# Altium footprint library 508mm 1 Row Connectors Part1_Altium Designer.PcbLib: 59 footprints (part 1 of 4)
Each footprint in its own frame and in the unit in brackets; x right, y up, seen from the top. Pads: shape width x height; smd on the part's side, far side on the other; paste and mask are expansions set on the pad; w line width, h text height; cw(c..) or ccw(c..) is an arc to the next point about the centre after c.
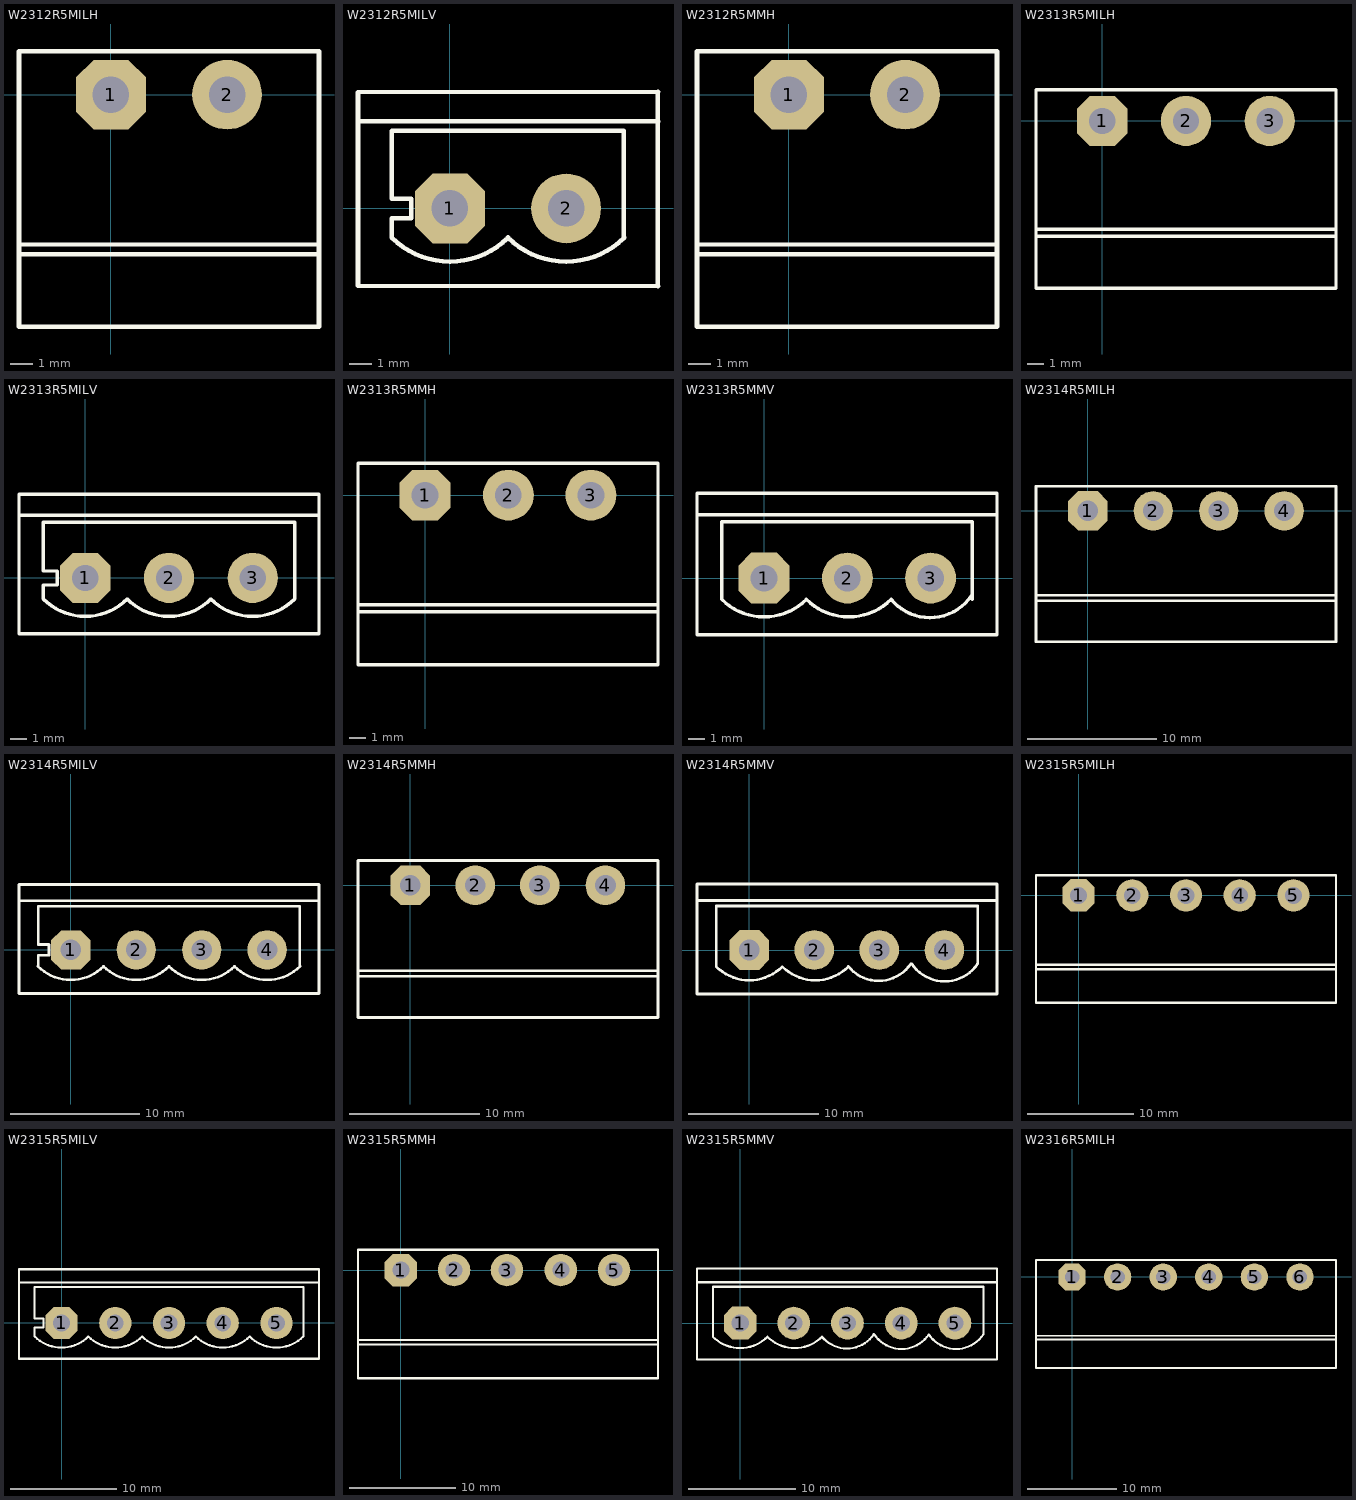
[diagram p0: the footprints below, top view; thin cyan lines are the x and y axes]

## W2312R5MILH [mil] "M.Hariri (Altium Designer)"
pads (2):
  oct 120x120 hole 62.99: 1(0,0)
  round 120 hole 62.99: 2(200,0)
Top Overlay:
  lines w8: -158.33,-275 355,-275 ; -158.33,-258.33 357.5,-257.5 ; -158.33,-400 358.33,-400 358.33,75 -158.33,75 -158.33,-400

## W2312R5MILV [mil] "M.Hariri (Altium Designer)"
pads (2):
  oct 120x120 hole 62.99: 1(0,0)
  round 120 hole 62.99: 2(200,0)
Top Overlay:
  lines w8: -158.33,150 358.27,149.61 ; -100.17,-50.17 ccw(c0,50) 100.17,-50.17 ; -100,-50 -100,-16.67 -66.67,-16.67 -66.67,16.67 -100,16.67 -100,133.33 299.21,133.86 ; 99.83,-50.17 ccw(c200,50) 300.17,-50.17 ; 299.21,-50 299.21,133.33 ; 357.55,-133.33 357.55,200 ; 358.27,-133.86 -158.33,-133.33 -158.33,200 358.27,200.79

## W2312R5MMH [mil] "M.Hariri (Altium Designer)"
pads (2):
  oct 120x120 hole 62.99: 1(0,0)
  round 120 hole 62.99: 2(200,0)
Top Overlay:
  lines w8: -158.33,-275 355,-275 ; -158.33,-258.33 357.5,-257.5 ; -158.33,-400 -158.33,75 358.33,75 358.33,-400 -158.33,-400

## W2313R5MILH [mil] "M.Hariri (Altium Designer)"
pads (3):
  oct 120x120 hole 62.99: 1(0,0)
  round 120 hole 62.99: 2(200,0) 3(400,0)
Top Overlay:
  lines w8: -158.33,-275 558.33,-275 ; -158.33,-258.33 558.33,-258.33 ; -158.33,-400 558.33,-400 558.33,75 -158.33,75 -158.33,-400

## W2313R5MILV [mil] "M.Hariri (Altium Designer)"
pads (3):
  oct 120x120 hole 62.99: 1(0,0)
  round 120 hole 62.99: 2(200,0) 3(400,0)
Top Overlay:
  lines w8: -158.33,150 558.33,150 ; -100.17,-50.17 ccw(c0,50) 100.17,-50.17 ; -100,-50 -100,-16.67 -66.67,-16.67 -66.67,16.67 -100,16.67 -100,133.33 500,133.33 500,-50 ; 99.83,-50.17 ccw(c200,50) 300.17,-50.17 ; 299.83,-50.17 ccw(c400,50) 500.17,-50.17 ; -158.33,-133.33 -158.33,200 558.33,200 558.33,-133.33 -158.33,-133.33

## W2313R5MMH [mil] "M.Hariri (Altium Designer)"
pads (3):
  oct 120x120 hole 62.99: 1(0,0)
  round 120 hole 62.99: 2(196.67,0) 3(391.67,0)
Top Overlay:
  lines w8: -158.33,-275 550,-275 ; -158.33,-258.33 550,-258.33 ; -158.33,-400 550,-400 550,75 -158.33,75 -158.33,-400

## W2313R5MMV [mil] "M.Hariri (Altium Designer)"
pads (3):
  oct 120x120 hole 62.99: 1(0,0)
  round 120 hole 62.99: 2(196.67,0) 3(393.33,0)
Top Overlay:
  lines w8: -158.33,150 550,150 ; -100.17,-50.17 ccw(c0,50) 100.17,-50.17 ; -100,-50 -100,133.33 491.67,133.33 491.67,-50 ; 99.83,-50.17 ccw(c200,50) 300.17,-50.17 ; 299.7,-49.47 ccw(c391.67,25) 489.77,-41.17 ; -158.33,-133.33 -158.33,200 550,200 550,-133.33 -158.33,-133.33

## W2314R5MILH [mil] "M.Hariri (Altium Designer)"
pads (4):
  oct 120x120 hole 62.99: 1(0,0)
  round 120 hole 62.99: 2(200,0) 3(400,0) 4(600,0)
Top Overlay:
  lines w8: -158.33,-275 758.33,-275 ; -158.33,-258.33 758.33,-258.33 ; -158.33,-400 758.33,-400 758.33,75 -158.33,75 -158.33,-400

## W2314R5MILV [mil] "M.Hariri (Altium Designer)"
pads (4):
  oct 120x120 hole 62.99: 1(0,0)
  round 120 hole 62.99: 2(200,0) 3(400,0) 4(600,0)
Top Overlay:
  lines w8: -158.33,150 758.33,150 ; -100.17,-50.17 ccw(c0,50) 100.17,-50.17 ; -100,-50 -100,-16.67 -66.67,-16.67 -66.67,16.67 -100,16.67 -100,133.33 700,133.33 700,-50 ; 99.83,-50.17 ccw(c200,50) 300.17,-50.17 ; 299.83,-50.17 ccw(c400,50) 500.17,-50.17 ; 499.83,-50.17 ccw(c600,50) 700.17,-50.17 ; -158.33,-133.33 758.33,-133.33 758.33,200 -158.33,200 -158.33,-133.33

## W2314R5MMH [mil] "M.Hariri (Altium Designer)"
pads (4):
  oct 120x120 hole 62.99: 1(0,0)
  round 120 hole 62.99: 2(196.67,0) 3(391.67,0) 4(590.83,0)
Top Overlay:
  lines w8: -158.33,-275 750,-275 ; -158.33,-258.33 750,-258.33 ; -158.33,-400 750,-400 750,75 -158.33,75 -158.33,-400

## W2314R5MMV [mil] "M.Hariri (Altium Designer)"
pads (4):
  oct 120x120 hole 62.99: 1(0,0)
  round 120 hole 62.99: 2(196.67,0) 3(393.33,0) 4(590.83,0)
Top Overlay:
  lines w8: -158.33,150 750,150 ; -100.17,-50.17 ccw(c0,50) 100.17,-50.17 ; -100,-50 -100,133.33 691.67,133.33 691.67,-41.67 ; 99.83,-50.17 ccw(c200,50) 300.17,-50.17 ; 299.7,-49.47 ccw(c391.67,25) 489.77,-41.17 ; 492.18,-42.1 ccw(c591.67,25) 691.15,-42.1 ; -158.33,-133.33 -158.33,200 750,200 750,-133.33 -158.33,-133.33

## W2315R5MILH [mil] "M.Hariri (Altium Designer)"
pads (5):
  oct 120x120 hole 62.99: 1(0,0)
  round 120 hole 62.99: 2(200,0) 3(400,0) 4(600,0) 5(800,0)
Top Overlay:
  lines w8: -158.33,-275 958.33,-275 ; -158.33,-258.33 958.33,-258.33 ; -158.33,-400 958.33,-400 958.33,75 -158.33,75 -158.33,-400

## W2315R5MILV [mil] "M.Hariri (Altium Designer)"
pads (5):
  oct 120x120 hole 62.99: 1(0,0)
  round 120 hole 62.99: 2(200,0) 3(400,0) 4(600,0) 5(800,0)
Top Overlay:
  lines w8: -158.33,150 958.33,150 ; -100.17,-50.17 ccw(c0,50) 100.17,-50.17 ; -100,-50 -100,-16.67 -66.67,-16.67 -66.67,16.67 -100,16.67 -100,133.33 900,133.33 900,-50 ; 99.83,-50.17 ccw(c200,50) 300.17,-50.17 ; 299.83,-50.17 ccw(c400,50) 500.17,-50.17 ; 499.83,-50.17 ccw(c600,50) 700.17,-50.17 ; 699.83,-50.17 ccw(c800,50) 900.17,-50.17 ; -158.33,-133.33 -158.33,200 958.33,200 958.33,-133.33 -158.33,-133.33

## W2315R5MMH [mil] "M.Hariri (Altium Designer)"
pads (5):
  oct 120x120 hole 62.99: 1(0,0)
  round 120 hole 62.99: 2(196.67,0) 3(391.67,0) 4(590.83,0) 5(787.5,0)
Top Overlay:
  lines w8: -158.33,-275 950,-275 ; -158.33,-258.33 950,-258.33 ; -158.33,-400 950,-400 950,75 -158.33,75 -158.33,-400

## W2315R5MMV [mil] "M.Hariri (Altium Designer)"
pads (5):
  oct 120x120 hole 62.99: 1(0,0)
  round 120 hole 62.99: 2(196.67,0) 3(393.33,0) 4(590.83,0) 5(787.5,0)
Top Overlay:
  lines w8: -158.33,150 941.67,150 ; -100.17,-50.17 ccw(c0,50) 100.17,-50.17 ; -100,-50 -100,133.33 891.67,133.33 891.67,-41.67 ; 99.83,-50.17 ccw(c200,50) 300.17,-50.17 ; 299.7,-49.47 ccw(c391.67,25) 489.77,-41.17 ; 492.18,-42.1 ccw(c591.67,25) 691.15,-42.1 ; 692.18,-42.1 ccw(c791.67,25) 891.15,-42.1 ; -158.33,-133.33 -158.33,200 941.67,200 941.67,-133.33 -158.33,-133.33

## W2316R5MILH [mil] "M.Hariri (Altium Designer)"
pads (6):
  oct 120x120 hole 62.99: 1(0,0)
  round 120 hole 62.99: 2(200,0) 3(400,0) 4(600,0) 5(800,0) 6(1000,0)
Top Overlay:
  lines w8: -158.33,-275 1158.33,-275 ; -158.33,-258.33 1158.33,-258.33 ; -158.33,-400 1158.33,-400 1158.33,75 -158.33,75 -158.33,-400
